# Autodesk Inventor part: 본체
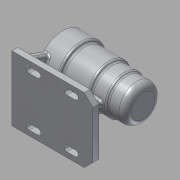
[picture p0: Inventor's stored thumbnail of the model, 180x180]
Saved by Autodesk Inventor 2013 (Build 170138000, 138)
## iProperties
Created: 2017-09
Part Number: 본체
Material: 알루미늄 6061
Document SubType Name: Modeling
Designer: Windows7
Density: 2.71 g/cm^3
Mass: 697.105 g
Surface Area: 710.312 cm^2
Volume: 257.234 cm^3
Author: Windows7
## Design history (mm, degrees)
sketch "스케치1"
  geometry: L1 (-56, 0)-(56, 0); L2 (56, 21)-(41, 21); L3 (41, 21)-(41, 24); L4 (41, 24)-(-13, 24); L5 (-13, 24)-(-13, 21); L6 (-13, 21)-(-25, 21); L7 (-25, 21)-(-25, 17.5); L8 (-25, 17.5)-(-43, 17.5); L9 (-43, 17.5)-(-43, 16); L10 (-43, 16)-(-47, 16); L11 (-47, 16)-(-47, 10.5); L12 (-47, 10.5)-(-50, 10.5); L13 (-50, 10.5)-(-50, 0); L14 (56, 21)-(56, 34); L15 (56, 34)-(28, 34); L16 (28, 34)-(28, 30); L17 (28, 30)-(-8, 30); L18 (-11, 27)-(-11, 27); L19 (-13.196, 27)-(-31, 27); L20 (-31, 27)-(-31, 25); L21 (-31, 25)-(-47, 25); L22 (-56, 16)-(-56, 0); A1 r 9 centre (-47, 16) between (-47, 25) and (-56, 16); A2 r 3 centre (-8, 27) between (-8, 30) and (-10.598, 28.5); A3 r 3 centre (-13.196, 30) between (-13.196, 27) and (-10.598, 28.5); 4 further points
  constraints: 44 end point, 12 parallel, 7 point on circle, 7 tangent, 6 perpendicular, 6 point on line, 3 centre point, 1 coincident, 1 collinear, 1 equal radius, 1 horizontal, 1 horizontal alignment, 1 midpoint
  dimensions: "d0" = 112 distance of L1.start L1.end; "d2" = 21 distance of L1.end L2.start; "d3" = 15 distance of L2.start L2.end; "d4" = 3 distance of L2.end L3.end; "d5" = 54 distance of L3.end L4.end; "d6" = 3 distance of L4.end L5.end; "d7" = 12 distance of L5.end L6.end; "d8" = 3.5 distance of L6.end L7.end; "d9" = 18 distance of L7.end L8.end; "d10" = 1.5 distance of L8.end L9.end; "d11" = 4 distance of L9.end L10.end; "d12" = 5.5 distance of L10.end L11.end; "d13" = 3 distance of L11.end L12.end; "d14" = 10.5 distance of L12.end L13.end; "d15" = 13 distance of L2.start L14.end; "d16" = 28 distance of L14.end L15.end; "d17" = 4 distance of L15.end L16.end; "d18" = 39 distance of L16.end point (-11, 30); "d19" = 3 distance of point (-11, 30) L18.end; "d20" = 20 distance of L18.end L19.end; "d21" = 2 distance of L19.end L20.end; "d22" = 25 distance of L20.end point (-56, 25); "d23" = 9 radius of A1; "d24" = 3 radius of A2
revolve "회전1" sketch "스케치1" stored, may be unused: angle "d25" = 90 deg
node "작업 평면1"
sketch "스케치2"
  geometry: L1 (-56, 45)-(56, 45); L2 (56, 45)-(56, -45); L3 (56, -45)-(-56, -45); L4 (-56, -45)-(-56, 45); 3 further points
  constraints: 8 end point, 2 midpoint, 2 parallel, 1 horizontal, 1 horizontal alignment, 1 perpendicular, 1 vertical alignment
  dimensions: "d27" = 112 distance of L1.start L1.end; "d29" = 90 distance of L1.end L2.end
extrude "돌출1" join sketch "스케치2" distance "d30" = 8; taper "d31" = 0 deg
sketch "스케치3"
  geometry: L1 (10, 8)-(23.1, 43.992); L2 (80, 8)-(66.9, 43.992); L3 (10, 8)-(80, 8); A1 r 34 centre (45, 70) between (23.1, 43.992) and (66.9, 43.992); 1 further point
  constraints: 6 end point, 2 point on circle, 1 centre point, 1 coincident, 1 horizontal
  dimensions: "d37" = 68 diameter of A1; "d38" = 70 deg angle of L2 L3; "d39" = 40 deg angle of L2 L1; "d41" = 11.68399 distance from line of point (45, 70) L2; "d42" = 62 distance from line of point (45, 70) L3; "d43" = 11.68399 distance from line of point (45, 70) L1
extrude "돌출2" join sketch "스케치3" distance "d44" = 8; taper "d45" = 0 deg
sketch "스케치4"
  geometry: L1 (34, -62)-(23.885, -24.25); L2 (34, -62)-(56, -62); L3 (56, -70)-(56, -62) reference; 1 further point
  constraints: 4 end point, 1 perpendicular
  dimensions: "d48" = 16.7947 distance from line of point (0, 0) L1; "d49" = 70.71068 distance of point (0, 0) L1.start; "d50" = 34.03739 distance of point (0, 0) L1.end
feature "리브1" sketch "스케치4" dims "d51" = 1, "d52" = 8, "d53" = 0, "d54" = 0, "d55" = 1, "d56" = 1
sketch "스케치5"
  geometry: L1 (34, -4)-(-48, -4) reference; L2 (56, -45)-(56, 45) reference; L3 (56, 45)-(-56, 45) reference; L4 (-48, 4)-(34, 4) reference; L5 (-56, -45)-(-56, 45) reference; L6 (-20, 30)-(-32, 30); L7 (-20, 38)-(-32, 38); L8 (32, 30)-(20, 30); L9 (32, 38)-(20, 38); L10 (32, -30)-(20, -30); L11 (32, -38)-(20, -38); L12 (-20, -30)-(-32, -30); L13 (-20, -38)-(-32, -38); A1 r 4 centre (-32, 34) between (-32, 38) and (-32, 30); A2 r 4 centre (-20, 34) between (-20, 30) and (-20, 38); A3 r 4 centre (20, 34) between (20, 38) and (20, 30); A4 r 4 centre (32, 34) between (32, 30) and (32, 38); A5 r 4 centre (20, -34) between (20, -30) and (20, -38); A6 r 4 centre (32, -34) between (32, -38) and (32, -30); A7 r 4 centre (-32, -34) between (-32, -30) and (-32, -38); A8 r 4 centre (-20, -34) between (-20, -38) and (-20, -30); 1 further point
  constraints: 18 tangent, 16 end point, 16 point on circle, 8 centre point, 3 parallel, 1 equal radius
  dimensions: "d59" = 8 diameter of A1; "d61" = 8 diameter of A2; "d63" = 8 diameter of A3; "d65" = 8 diameter of A4; "d66" = 90 deg angle of L2 L12; "d67" = 90 deg angle of L2 L13; "d68" = 15 distance between parallel lines of L3 L8; "d69" = 75 distance between parallel lines of L3 L10; "d70" = 75 distance from line of L2.end L12; "d71" = 83 distance from line of L2.end L13; "d72" = 24 distance from line of L9.start L2; "d73" = 42 distance from line of L9.start L1; "d74" = 24 distance from line of L10.start L2; "d75" = 36 distance from line of L10.end L2; "d76" = 76 distance from line of L7.start L2; "d77" = 42 distance from line of L7.start L1; "d78" = 76 distance from line of L12.start L2; "d79" = 88 distance from line of L12.end L2
extrude "돌출3" cut sketch "스케치5" distance "d80" = 8; taper "d81" = 0 deg
sketch "스케치6"
  geometry: L1 (90, 0)-(0, 0) reference; L2 (90, 0)-(90, 8) reference; 3 further points
  dimensions: "d86" = 57 distance from line of point (67.517, 57) L1; "d87" = 22.48334 distance from line of point (67.517, 57) L2; "d88" = 96 distance from line of point (45, 96) L1; "d89" = 45 distance from line of point (45, 96) L2; "d90" = 57 distance from line of point (22.483, 57) L1; "d91" = 67.51666 distance from line of point (22.483, 57) L2
hole "구멍1" sketch "스케치6" at (22.483, 57), (67.517, 57), (45, 96) diameter "d92" = 3.242; stored, may be unused: countersink angle "d96" = 90 deg, drill point angle "d98" = 118 deg; dims "d93" = 8, "d94" = 4, "d95" = 2, "d97" = 11
sketch "스케치7"
  geometry: L1 (112, 0)-(0, 0) reference; L2 (112, 0)-(112, 8) reference; 2 further points
  constraints: 1 other
  dimensions: "d101" = 70 distance from line of point (64, 70) L1; "d102" = 48 distance from line of point (64, 70) L2
feature "엠보싱1" sketch "스케치7" dims "d0" = 112, "d2" = 21, "d3" = 15, "d4" = 3, "d5" = 54, "d6" = 3, "d7" = 12, "d8" = 3.5, "d9" = 18, "d10" = 1.5, "d11" = 4, "d12" = 5.5, "d13" = 3, "d14" = 10.5, "d15" = 13, "d16" = 28, "d17" = 4, "d18" = 39, "d19" = 3, "d20" = 20, "d21" = 2, "d22" = 25, "d23" = 9, "d24" = 3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
chamfer "모따기1" distance "d105" = 12; stored, may be unused: second distance "d106" = 2, angle "d107" = 45 deg
chamfer "모따기2" distance "d108" = 1; stored, may be unused: second distance "d109" = 2, angle "d110" = 45 deg
fillet "모깎기1" dims "d111" = 3
fillet "모깎기2" dims "d112" = 0.3
fillet "모깎기3" dims "d113" = 3, "d114" = 2
fillet "모깎기4" dims "d115" = 3
node "솔리드1"
